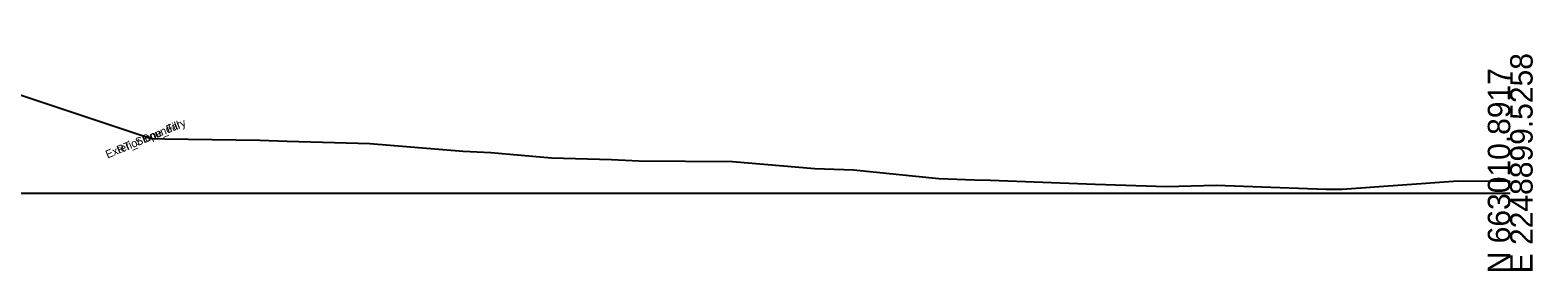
# Model space of a CAD drawing. Extents: x -26 to 2603, y -10 to 9566.
# Drawn here: x 1415.1 to 1602.8, y 1990.3 to 2020.3 of the extents above; entities that cross this region are included whole.
import ezdxf

# ---------------------------------------------------------------- set-up
doc = ezdxf.new("R2010")
doc.units = 0
for name, color, linetype in [('Exist Cross Section Cell', 7, 'Continuous'), ('Exist XS Ground Line', 7, 'Continuous'), ('Scratch_Level_9', 7, 'Continuous')]:
    doc.layers.add(name, color=color, linetype=linetype)

msp = doc.modelspace()

# ---------------------------------------------------------------- linework, layer by layer
at = {"layer": 'Exist Cross Section Cell'}
msp.add_line((1300, 2000), (1600, 2000), dxfattribs=at)
at = {"layer": 'Exist XS Ground Line'}
for p, q in [((1430.2, 2006.82), (1431.89, 2006.77)), ((1431.89, 2006.77), (1443.79, 2006.61)), ((1443.79, 2006.61), (1447.21, 2006.48)), ((1447.21, 2006.48), (1457.53, 2006.19)), ((1457.53, 2006.19), (1469.18, 2005.25)), ((1469.18, 2005.25), (1472.64, 2005.06)), ((1472.64, 2005.06), (1480.25, 2004.4)), ((1480.25, 2004.4), (1487.74, 2004.2)), ((1487.74, 2004.2), (1491.15, 2004.04)), ((1491.15, 2004.04), (1502.85, 2003.97)), ((1502.85, 2003.97), (1513.11, 2003.1)), ((1513.11, 2003.1), (1517.95, 2002.93)), ((1517.95, 2002.93), (1528.61, 2001.85)), ((1528.61, 2001.85), (1533.06, 2001.66)), ((1533.06, 2001.66), (1535.08, 2001.61)), ((1535.08, 2001.61), (1548.16, 2001.12)), ((1579.01, 2000.5), (1593.48, 2001.55)), ((1593.48, 2001.55), (1600, 2001.51)), ((1548.16, 2001.12), (1557.05, 2000.85)), ((1557.05, 2000.85), (1563.27, 2001)), ((1563.27, 2001), (1576.97, 2000.51)), ((1576.97, 2000.51), (1578.37, 2000.5)), ((1578.37, 2000.5), (1579.01, 2000.5))]:
    msp.add_line(p, q, dxfattribs=at)
msp.add_lwpolyline([(1389.59, 2020.35), (1430.2, 2006.82)], dxfattribs=at)

# ---------------------------------------------------------------- texts
at = {"layer": 'Exist Cross Section Cell'}
for s, p in [('E 2248899.5258', (1602.8, 1990)), ('N 663010.8917', (1600, 1990))]:
    msp.add_text(s, height=2.8, rotation=90, dxfattribs=at).set_placement(p)
at = {"layer": 'Scratch_Level_9'}
for s, p in [('Exterior Boundary', (1424.77, 2004.32)), ('Exterior Boundary', (1424.77, 2004.32)), ('RT_Slope_Fill', (1426.17, 2004.9)), ('RT_Slope_Fill', (1426.17, 2004.9))]:
    msp.add_text(s, height=1, rotation=22.5575, dxfattribs=at).set_placement(p)

doc.saveas('drawing.dxf')
